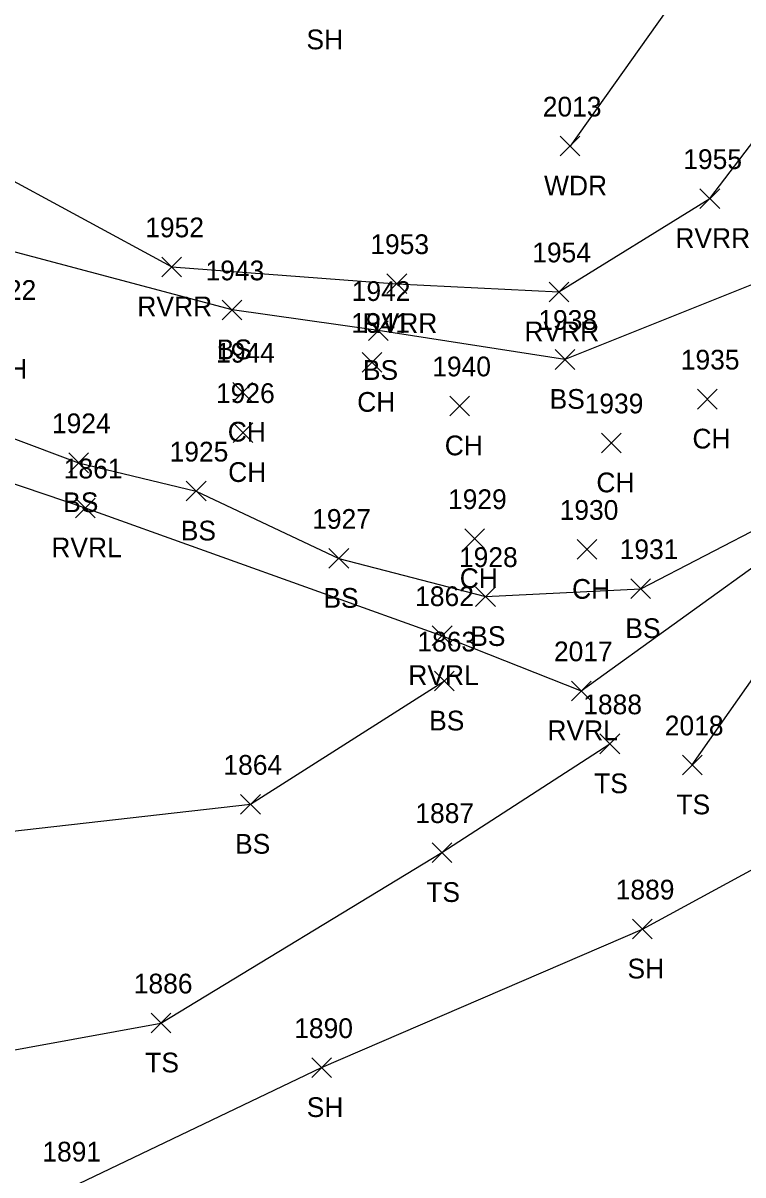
# Model space of a CAD drawing. Extents: x 1633660 to 1636532, y 388643 to 392631.
# Drawn here: x 1634542.2 to 1634615.1, y 388865.4 to 388982.1 of the extents above; entities that cross this region are included whole.
import ezdxf

# ---------------------------------------------------------------- set-up
doc = ezdxf.new("R2010")
doc.units = 0
for name, color, linetype in [('L_A', 7, 'Continuous'), ('L_I', 7, 'Continuous'), ('L_TIC', 7, 'Continuous'), ('LAWA', 7, 'Continuous'), ('LAWE', 7, 'Continuous'), ('LELB', 7, 'Continuous'), ('LSOGP', 7, 'Continuous')]:
    doc.layers.add(name, color=color, linetype=linetype)

msp = doc.modelspace()

# ---------------------------------------------------------------- linework, layer by layer
at = {"layer": 'L_TIC'}
for points in [[(1634596.62, 388968.61), (1634598.62, 388970.61)], [(1634598.62, 388968.61), (1634596.62, 388970.61)], [(1634610.77, 388963.29), (1634612.77, 388965.29)], [(1634612.77, 388963.29), (1634610.77, 388965.29)], [(1634556.27, 388956.37), (1634558.27, 388958.37)], [(1634558.27, 388956.37), (1634556.27, 388958.37)], [(1634579.07, 388954.67), (1634581.07, 388956.67)], [(1634581.07, 388954.67), (1634579.07, 388956.67)], [(1634595.48, 388953.83), (1634597.48, 388955.83)], [(1634597.48, 388953.83), (1634595.48, 388955.83)], [(1634562.38, 388952.01), (1634564.38, 388954.01)], [(1634564.38, 388952.01), (1634562.38, 388954.01)], [(1634577.19, 388949.92), (1634579.19, 388951.92)], [(1634579.19, 388949.92), (1634577.19, 388951.92)], [(1634576.56, 388946.69), (1634578.56, 388948.69)], [(1634578.56, 388946.69), (1634576.56, 388948.69)], [(1634596.1, 388946.99), (1634598.1, 388948.99)], [(1634598.1, 388946.99), (1634596.1, 388948.99)], [(1634563.45, 388943.67), (1634565.45, 388945.67)], [(1634565.45, 388943.67), (1634563.45, 388945.67)], [(1634610.52, 388942.97), (1634612.52, 388944.97)], [(1634612.52, 388942.97), (1634610.52, 388944.97)], [(1634585.43, 388942.28), (1634587.43, 388944.28)], [(1634587.43, 388942.28), (1634585.43, 388944.28)], [(1634563.49, 388939.58), (1634565.49, 388941.58)], [(1634565.49, 388939.58), (1634563.49, 388941.58)], [(1634600.79, 388938.53), (1634602.79, 388940.53)], [(1634602.79, 388938.53), (1634600.79, 388940.53)], [(1634546.83, 388936.52), (1634548.83, 388938.52)], [(1634548.83, 388936.52), (1634546.83, 388938.52)], [(1634558.74, 388933.65), (1634560.74, 388935.65)], [(1634560.74, 388933.65), (1634558.74, 388935.65)], [(1634547.51, 388931.94), (1634549.51, 388933.94)], [(1634549.51, 388931.94), (1634547.51, 388933.94)], [(1634586.95, 388928.83), (1634588.95, 388930.83)], [(1634588.95, 388928.83), (1634586.95, 388930.83)], [(1634598.34, 388927.74), (1634600.34, 388929.74)], [(1634600.34, 388927.74), (1634598.34, 388929.74)], [(1634573.19, 388926.83), (1634575.19, 388928.83)], [(1634575.19, 388926.83), (1634573.19, 388928.83)], [(1634588.05, 388922.96), (1634590.05, 388924.96)], [(1634590.05, 388922.96), (1634588.05, 388924.96)], [(1634603.77, 388923.76), (1634605.77, 388925.76)], [(1634605.77, 388923.76), (1634603.77, 388925.76)], [(1634583.66, 388919), (1634585.66, 388921)], [(1634585.66, 388919), (1634583.66, 388921)], [(1634583.89, 388914.4), (1634585.89, 388916.4)], [(1634585.89, 388914.4), (1634583.89, 388916.4)], [(1634597.75, 388913.41), (1634599.75, 388915.41)], [(1634599.75, 388913.41), (1634597.75, 388915.41)], [(1634600.64, 388908.04), (1634602.64, 388910.04)], [(1634602.64, 388908.04), (1634600.64, 388910.04)], [(1634608.99, 388905.9), (1634610.99, 388907.9)], [(1634610.99, 388905.9), (1634608.99, 388907.9)], [(1634564.24, 388901.91), (1634566.24, 388903.91)], [(1634566.24, 388901.91), (1634564.24, 388903.91)], [(1634583.64, 388897.02), (1634585.64, 388899.02)], [(1634585.64, 388897.02), (1634583.64, 388899.02)], [(1634603.94, 388889.27), (1634605.94, 388891.27)], [(1634605.94, 388889.27), (1634603.94, 388891.27)], [(1634555.17, 388879.75), (1634557.17, 388881.75)], [(1634557.17, 388879.75), (1634555.17, 388881.75)], [(1634571.45, 388875.23), (1634573.45, 388877.23)], [(1634573.45, 388875.23), (1634571.45, 388877.23)]]:
    msp.add_lwpolyline(points, dxfattribs=at)
at = {"layer": 'LAWA'}
msp.add_lwpolyline([(1634777.74, 389176.81), (1634754.17, 389147.84), (1634723.8, 389118.19), (1634689.85, 389088.67), (1634673.22, 389058.41), (1634669.47, 389042.78), (1634646.69, 389025.62), (1634627.54, 389002.43), (1634610.06, 388987.13), (1634597.62, 388969.61)], dxfattribs=at)
at = {"layer": 'LAWE'}
for points in [[(1634485.27, 388945.87), (1634504.2, 388941.24), (1634525.53, 388940.73), (1634548.51, 388932.94), (1634584.66, 388920), (1634598.75, 388914.41), (1634618.8, 388928.88), (1634638.3, 388944.91), (1634660.99, 388957.08), (1634677.58, 388983.24), (1634696.95, 389006.4), (1634707.36, 389033.31), (1634727.93, 389056.72), (1634749.89, 389078.7), (1634762.92, 389095.06), (1634797.9, 389102.54), (1634816.33, 389112.04), (1634824.18, 389130.77), (1634824.18, 389150.65), (1634818.45, 389174.95), (1634815.05, 389205.92), (1634802.11, 389220.82), (1634788.76, 389226.82)], [(1634520.43, 388972.83), (1634529.58, 388972.39), (1634557.27, 388957.37), (1634580.07, 388955.67), (1634596.48, 388954.83), (1634611.77, 388964.29), (1634628.48, 388986.24), (1634647.88, 389006.91), (1634658.84, 389024.3), (1634672.7, 389044.33), (1634690.56, 389064.6), (1634720.63, 389097.89), (1634743.8, 389121.88), (1634765.96, 389139.81), (1634789.88, 389159.93), (1634790.78, 389168.23), (1634779.52, 389189.43), (1634780.72, 389197.89), (1634770.08, 389207.77)]]:
    msp.add_lwpolyline(points, dxfattribs=at)
at = {"layer": 'LELB'}
for points in [[(1634609.99, 388906.9), (1634623.86, 388926.68), (1634649.49, 388937.05), (1634665.45, 388952.5), (1634695.16, 388960.07), (1634729.71, 388982.06), (1634750.63, 388992.22), (1634777.03, 389014.48), (1634810.97, 389037.99)], [(1634617.86, 388956.31), (1634597.1, 388947.99), (1634578.19, 388950.92), (1634563.38, 388953.01), (1634537.32, 388959.95), (1634518.55, 388966.68)], [(1634486.03, 388958.42), (1634504.06, 388945.03), (1634527.82, 388945.02), (1634547.83, 388937.52), (1634559.74, 388934.65), (1634574.19, 388927.83), (1634589.05, 388923.96), (1634604.77, 388924.76), (1634617.83, 388931.52), (1634629.87, 388942.08)], [(1634584.89, 388915.4), (1634565.24, 388902.91), (1634528.64, 388898.73), (1634496.98, 388906.62), (1634477.85, 388894.65), (1634446.93, 388893.09), (1634415.16, 388876.74), (1634407.22, 388862.91), (1634384.25, 388848.4), (1634365.18, 388835.86)], [(1634366.11, 388829.23), (1634392.92, 388840.96), (1634414.75, 388860.24), (1634439.48, 388873.42), (1634473.36, 388870.48), (1634511.37, 388872.55), (1634556.17, 388880.75), (1634584.64, 388898.02), (1634601.64, 388909.04)]]:
    msp.add_lwpolyline(points, dxfattribs=at)
at = {"layer": 'LSOGP'}
msp.add_lwpolyline([(1634218.98, 388740.85), (1634254.67, 388740.24), (1634315.25, 388739.85), (1634380.93, 388763.62), (1634394.19, 388796.15), (1634428.1, 388811.92), (1634452.29, 388827.49), (1634483.59, 388839.11), (1634515.33, 388848.44), (1634546.28, 388863.72), (1634572.45, 388876.23), (1634604.94, 388890.27), (1634644.29, 388911.66), (1634697.95, 388942.99), (1634729.71, 388982.06), (1634750.63, 388992.22), (1634777.03, 389014.48), (1634810.97, 389037.99), (1634811.65, 389038.97), (1634835.21, 389072.38), (1634837.85, 389085.95), (1634849.33, 389112.53), (1634851.42, 389137.05)], dxfattribs=at)

# ---------------------------------------------------------------- texts
at = {"layer": 'L_A'}
for s, p in [('SH', (1634570.91, 388979.42)), ('WDR', (1634594.98, 388964.61)), ('RVRR', (1634608.28, 388959.29)), ('RVRR', (1634553.78, 388952.37)), ('RVRR', (1634576.59, 388950.67)), ('RVRR', (1634592.99, 388949.83)), ('BS', (1634561.82, 388948.01)), ('CH', (1634538.77, 388946.03)), ('BS', (1634576.63, 388945.92)), ('CH', (1634576.05, 388942.69)), ('BS', (1634595.54, 388942.99)), ('CH', (1634562.94, 388939.67)), ('CH', (1634584.92, 388938.28)), ('CH', (1634610.01, 388938.97)), ('CH', (1634562.98, 388935.58)), ('CH', (1634600.28, 388934.53)), ('BS', (1634546.27, 388932.52)), ('BS', (1634558.18, 388929.65)), ('RVRL', (1634545.07, 388927.94)), ('CH', (1634586.44, 388924.83)), ('BS', (1634572.63, 388922.83)), ('CH', (1634597.82, 388923.74)), ('BS', (1634603.21, 388919.76)), ('BS', (1634587.5, 388918.96)), ('RVRL', (1634581.23, 388915)), ('BS', (1634583.34, 388910.4)), ('RVRL', (1634595.32, 388909.41)), ('TS', (1634600.05, 388904.04)), ('TS', (1634608.39, 388901.9)), ('BS', (1634563.68, 388897.91)), ('TS', (1634583.05, 388893.02)), ('SH', (1634603.43, 388885.27)), ('TS', (1634554.58, 388875.75)), ('SH', (1634570.94, 388871.23))]:
    msp.add_text(s, height=2, dxfattribs=at).set_placement(p)
at = {"layer": 'L_I'}
for s, p in [('2013', (1634594.85, 388972.61)), ('1955', (1634609.08, 388967.29)), ('1952', (1634554.58, 388960.37)), ('1953', (1634577.38, 388958.67)), ('1954', (1634593.78, 388957.83)), ('1943', (1634560.69, 388956.01)), ('1922', (1634537.59, 388954.03)), ('1942', (1634575.5, 388953.92)), ('1938', (1634594.4, 388950.99)), ('1941', (1634575.44, 388950.69)), ('1944', (1634561.76, 388947.67)), ('1940', (1634583.65, 388946.28)), ('1935', (1634608.83, 388946.97)), ('1926', (1634561.75, 388943.58)), ('1939', (1634599.09, 388942.53)), ('1924', (1634545.13, 388940.52)), ('1925', (1634557.05, 388937.65)), ('1861', (1634546.33, 388935.94)), ('1929', (1634585.25, 388932.83)), ('1930', (1634596.56, 388931.74)), ('1927', (1634571.49, 388930.83)), ('1931', (1634602.64, 388927.76)), ('1928', (1634586.36, 388926.96)), ('1862', (1634581.92, 388923)), ('1863', (1634582.15, 388918.4)), ('2017', (1634595.98, 388917.41)), ('1888', (1634598.95, 388912.04)), ('2018', (1634607.21, 388909.9)), ('1864', (1634562.5, 388905.91)), ('1887', (1634581.94, 388901.02)), ('1889', (1634602.24, 388893.27)), ('1886', (1634553.42, 388883.75)), ('1890', (1634569.67, 388879.23)), ('1891', (1634544.16, 388866.72))]:
    msp.add_text(s, height=2, dxfattribs=at).set_placement(p)

doc.saveas('drawing.dxf')
